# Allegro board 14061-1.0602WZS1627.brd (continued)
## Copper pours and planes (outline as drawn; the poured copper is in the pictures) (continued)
DCBATOUT on BOTTOM: 57.07,64.12 56.88,64.31 56.88,69.22 57.26,69.6 61.32,69.6 61.58,69.34 61.58,64.26 61.44,64.12
DCBATOUT on L3: 53.51,72.02 54.74,70.79 54.74,70.76 55.02,70.48 59.98,70.48 60.61,69.85 60.61,68.17 59.75,67.31 50.96,67.31 50.68,67.03 48.17,67.03 47.89,67.31 46.52,67.31 46.24,67.03 43.95,67.03 41.56,69.42 41.56,71.77 41.82,72.02
DCBATOUT on L3: 144.31,142.88 144.31,127.38 143.92,127 143.92,119.61 144.4,119.13 144.4,115.34 144.4,115.34 144.4,114.63 145.7,113.33 145.7,111.28 146.11,110.87 146.11,110.34 146.92,109.52 148.55,109.52 148.88,109.86 148.88,111.58 148.15,112.31 148.15,114.8 146.74,116.2 146.74,124.18 146.92,124.36 146.97,124.36 147.99,125.37 147.99,129.92 148.14,130.07 148.14,142.7 147.58,143.26 144.69,143.26
DCBATOUT on L4: 54.77,67.18 52.87,69.09 42.32,69.09 41.82,68.58 35.35,68.58 33.41,66.63 33.41,59.45 37.4,55.46 37.4,52.28 36.97,51.85 35.56,51.85 30.49,56.92 30.49,68.12 36.99,74.62 43.55,74.62 44.48,75.55 44.48,77.85 43.98,78.36 41.63,78.36 40.43,79.56 40.43,118.31 40.44,118.32 40.44,118.82 42.09,120.47 42.09,124.61 43.23,125.74 43.24,125.74 43.74,126.24 46.97,126.24 47.85,125.36 47.85,119.64 46.71,118.5 46.71,86.22 51.47,81.45 51.47,80.14 51.47,79.11 52.48,78.11 53.51,78.11 60.6,71.02 60.6,67.74 60.05,67.18 ; 1 cut-out
DCBATOUT_1D8V on TOP: 31.1,209.19 30.74,209.55 30.74,214.71 30.12,215.33 29.94,215.33 29.88,215.39 29.88,216.31 29.45,216.74 29.45,222.78 29.67,223.01 33.41,223.01 33.68,222.75 33.68,220.56 35.42,218.82 35.42,215.9 36.36,214.96 36.36,209.37 36.18,209.19 ; 2 cut-outs
DCBATOUT_1D8V on BOTTOM: 30.84,219.25 30.18,219.91 30.18,222.88 30.36,223.06 33.64,223.06 33.99,222.71 33.99,220.12 33.13,219.25
DDR_VDDQ on TOP: 86.58,160.14 86.35,160.37 86.35,160.52 87.19,161.36 87.57,161.36 87.98,160.95 87.98,160.67 87.45,160.14
DDR_VDDQ on TOP: 87.18,168.66 86.37,169.47 86.37,169.65 86.55,169.82 87.36,169.82 87.94,169.24 87.94,169.06 87.54,168.66
DDR_VDDQ on BOTTOM: 132.34,147.9 131.74,148.5 95.7,148.5 93.53,150.67 92.23,150.67 88.81,154.09 88.81,158.88 87.36,160.32 87.36,160.99 87.52,161.15 88.13,161.15 88.71,160.57 90.36,160.57 90.93,161.14 92.48,161.14 92.81,161.48 92.81,162.33 92.97,162.49 93.65,162.49 93.91,162.75 93.91,164.07 94.51,164.66 94.51,165.08 94.83,165.4 94.83,165.68 95.08,165.93 95.08,167.07 94.92,167.23 94.11,167.23 93.99,167.36 93.99,168.15 93.85,168.28 93.65,168.28 93.64,168.29 87.75,168.29 87.43,168.61 87.43,169.34 87.84,169.75 87.84,176.86 89.14,178.16 89.14,179.17 91.52,181.56 97.85,181.56 98.97,182.68 130.59,182.68 130.77,182.5 130.77,176.58 131.33,176.02 133.08,176.02 133.15,176.1 134.15,176.1 135.24,175.01 136.81,175.01 136.81,175.02 137.7,175.91 139.56,175.91 140.19,175.27 140.19,154.48 140.95,153.72 140.95,151.21 140.33,150.58 140.33,149.9 138.34,147.9 ; 38 cut-outs
DPLL_PVDD on TOP: 90.51,98.02 90.38,98.15 90.38,99.9 90.94,100.46 90.94,102.03 91.17,102.26 91.73,102.26 92.13,101.85 92.13,101.52 91.96,101.35 91.96,100.81 92.24,100.53 92.24,99.95 91.92,99.63 91.92,99.45 92.11,99.26 92.11,98.98 91.65,98.53 91.22,98.53 90.71,98.02
DPLL_PVDD on BOTTOM: 94.14,96.06 93.84,96.37 93.23,96.37 92.77,96.82 92.77,97.43 92.08,98.12 92.08,98.45 91.65,98.88 91.65,100.56 91.5,100.71 91.5,101.68 91.65,101.83 92.08,101.83 92.21,101.7 92.21,100.84 92.54,100.51 92.97,100.51 93.1,100.38 93.1,98.86 93.68,98.27 93.68,97.49 94.19,96.98 94.7,96.98 94.93,96.75 94.93,96.32 94.67,96.06 ; 3 cut-outs
DPLL_VDDC on TOP: 91.09,102.49 90.84,102.74 90.84,103.12 90.33,103.63 90.33,104.27 90.58,104.52 91.6,104.52 92.11,104.01 92.11,103.5 91.6,103 91.6,102.62 91.47,102.49
DPLL_VDDC on BOTTOM: 90.69,103.35 90.61,103.43 90.61,103.76 90.86,104.01 90.86,104.65 91.83,105.61 93,105.61 93.45,106.07 93.45,107.72 93.71,107.98 95.08,107.98 95.24,107.81 95.24,104.91 94.8,104.47 92.74,104.47 92.41,104.14 92.41,103.58 92.18,103.35 ; 2 cut-outs
DPLL_VDDC on L4: 90.33,103.68 90.21,103.56 90.21,103.35 89.01,103.35 88.65,103 88.65,99.77 89.09,99.34 89.09,97.44 89.28,97.24 91.06,97.24 91.51,97.69 91.51,99.3 91.5,99.31 91.5,99.95 92.72,101.17 92.72,103.89 92.46,104.14 90.61,104.14 90.33,103.86
ISW_1 on BOTTOM: 39.96,35 39.78,35.18 39.78,38.23 39.25,38.76 37.09,38.76 36.71,38.38 36.71,36.7 35.47,35.46 33.94,35.46 33.82,35.59 33.82,36.47 34.22,36.88 34.96,36.88 35.62,37.54 35.62,42.85 36.28,43.51 41.41,43.51 41.94,42.98 41.94,35.13 41.82,35
LX on TOP: 29.75,35.46 29.75,43.56 30.01,43.81 30.03,43.81 31.02,44.81 34.17,44.81 34.81,44.17 34.81,43.16 33.78,42.13 33.78,35.63 33.33,35.18 30.03,35.18
LX on BOTTOM: 31.96,37.29 31.86,37.39 31.86,38.48 31.35,38.99 29.37,38.99 28.99,39.37 28.99,43.43 29.37,43.81 29.37,43.81 29.82,44.26 35.09,44.26 35.3,44.05 35.3,43.47 34.45,42.62 34.45,38.23 34.44,38.21 34.44,37.73 33.99,37.29
MCT_R on TOP: 59.98,9.65 59.85,9.78 59.85,14.1 59.98,14.22 63.93,14.22 64.15,14.44 64.15,17.89 64.29,18.03 66.34,18.03 66.45,17.92 66.45,14.61 64.55,12.7 63.41,12.7 63.28,12.57 63.28,10.41 62.52,9.65 ; 2 cut-outs
MCT_R_1 on BOTTOM: 64.3,11.68 64.17,11.81 64.17,17.91 64.3,18.03 66.33,18.03 66.45,17.91 66.45,11.94 66.2,11.68
MEM_VTT on TOP: 141.04,129.25 140.56,129.73 140.56,130.32 140.57,130.32 141.26,131.01 141.26,139.7 141.64,140.08 145.96,140.08 146.21,139.83 146.21,138.56 146.08,138.43 143.29,138.43 142.91,138.05 142.91,130.42 141.74,129.25
MEM_VTT on BOTTOM: 133.97,128.27 133.71,128.52 131.33,128.52 131.25,128.6 131.25,129.36 131.33,129.44 137.78,129.44 138.41,130.07 141.38,130.07 141.69,129.77 141.69,129.46 141.1,128.88 140.95,128.88 140.34,128.27 ; 9 cut-outs
MPV18 on BOTTOM: 78.75,87.3 78.62,87.43 78.62,92.23 78.42,92.44 78.01,92.44 77.91,92.54 77.91,93.1 78.01,93.2 78.54,93.2 78.97,92.77 78.97,92.28 79.18,92.08 79.18,91.04 79.3,90.91 79.3,87.41 79.2,87.3
PWR_0P95V_LX on TOP: 118.91,106.3 118.52,106.68 118.52,112.78 118.78,113.03 120.94,113.03 121.57,113.67 121.57,114.94 121.83,115.19 123.22,115.19 123.35,115.06 123.35,113.41 123.48,113.28 124.87,113.28 125.13,113.03 125.13,109.47 125,109.35 123.99,109.35 123.35,108.71 123.35,106.43 123.22,106.3
PWR_0P95V_VIN on TOP: 123.99,104.9 123.86,105.03 123.86,108.58 124.11,108.84 130.59,108.84 130.84,108.58 130.84,105.16 130.59,104.9
PWR_1D15V_A on TOP: 92.87,203.84 91.73,204.98 91.73,210.69 91.98,210.95 96.55,210.95 96.93,210.57 96.93,204.34 96.43,203.84 ; 6 cut-outs
PWR_1D15V_LX on TOP: 92.74,214.76 92.62,214.88 92.62,219.07 92.74,219.2 94.01,219.2 94.39,218.82 96.17,218.82 96.22,218.77 96.22,217.68 97.11,216.79 97.11,215.11 96.76,214.76
PWR_1D15V_PVIN on TOP: 91.37,221.11 90.99,221.49 90.99,224.59 91.17,224.76 93.53,224.76 93.66,224.64 93.66,223.39 94.36,222.68 95.56,222.68 95.79,222.45 95.79,221.16 95.74,221.11 ; 4 cut-outs
PWR_1P05V_LX on TOP: 37.75,195.83 37.37,196.22 37.37,199.01 37.22,199.16 36.18,199.16 36.05,199.29 36.05,200.69 36.18,200.81 38.08,200.81 38.34,201.07 38.34,202.46 38.46,202.59 42.02,202.59 42.15,202.46 42.15,201.45 42.65,200.94 45.19,200.94 45.27,200.86 45.27,199.39 45.32,199.34 45.32,196.75 44.41,195.83 ; 2 cut-outs
PWR_1P05V_LX on L3: 38.51,202.56 41.94,202.56 42.07,202.44 42.07,201.55 42.71,200.91 45.25,200.91 45.25,196.72 44.36,195.83 37.75,195.83 37.37,196.22 37.37,199.01 37.24,199.14 36.23,199.14 36.1,199.26 36.1,200.66 36.23,200.79 38.01,200.79 38.39,201.17 38.39,202.44
PWR_1P05V_VIN on TOP: 43.06,201.22 42.71,201.57 42.71,212.01 43.04,212.34 47.89,212.34 48.12,212.12 48.12,207.92 48.39,207.65 48.39,204.95 47.96,204.52 47.12,204.52 46.79,204.19 46.79,201.47 46.54,201.22
PWR_3V_PHASE2 on TOP: 77.38,48.59 77.25,48.72 77.25,50.83 77.43,51 79.15,51 79.54,51.38 79.54,53.04 79.28,53.29 75.73,53.29 75.73,56.59 75.85,56.72 77.38,56.72 77.5,56.85 77.5,58.88 77.63,59 82.46,59 83.09,58.37 83.09,48.84 82.84,48.59
PWR_5V_PHASE1 on TOP: 78.11,59.84 77.5,60.45 77.5,62.74 77.63,62.87 79.03,62.87 79.54,63.37 79.54,64.9 79.28,65.15 75.98,65.15 75.85,65.28 75.85,68.71 76.11,68.96 78.77,68.96 79.03,69.22 79.03,70.59 79.26,70.83 82.7,70.83 83.6,69.93 83.6,60.15 83.29,59.84
PWR_CHG_PHASE on BOTTOM: 38.26,54.99 38.13,55.12 38.13,57.66 37.75,58.04 36.15,58.04 36.1,57.99 36.1,56.74 36,56.64 34.07,56.64 33.82,56.9 33.82,58.55 34.32,59.05 34.32,61.98 34.58,62.23 40.55,62.23 41.18,61.59 41.18,59.31 41.82,58.67 41.82,55.12 41.69,54.99
PWR_DDR4_LDOIN on TOP: 150.55,136.17 150.3,136.42 149.34,136.42 148.68,137.08 148.68,137.94 148.72,137.98 148.75,137.98 148.75,138.46 149,138.71 149.94,138.71 150.2,138.46 150.2,137.46 151.19,136.47 151.19,136.32 151.04,136.17
PWR_DDR4_LX on TOP: 153.27,150.85 152.94,151.18 152.94,154.56 152.69,154.81 148.62,154.81 148.37,155.07 148.37,156.67 148.22,156.82 148.22,158.98 149.13,159.89 158.78,159.89 159.04,159.64 159.04,151.03 158.86,150.85 ; 2 cut-outs
PWR_DDR4_VIN on TOP: 148.6,144.07 148.16,144.5 144.26,144.5 144.16,144.6 144.16,153.67 144.88,154.39 152.1,154.39 152.18,154.31 152.18,144.4 151.85,144.07
PWR_DDR4_VIN on BOTTOM: 147.4,144.4 146.79,145.01 146.79,148.41 147.1,148.72 152.05,148.72 152.18,148.59 152.18,144.53 152.05,144.4
PWR_DDR4_VTT on TOP: 147.1,134.24 146.85,134.49 146.85,139.95 146.97,140.08 147.99,140.08 148.12,139.95 148.12,137.39 149.32,136.18 149.47,136.18 149.64,136.02 149.64,135.89 149.51,135.76 149.23,135.76 148.62,135.16 148.62,134.37 148.5,134.24
PWR_V1P5A on BOTTOM: 163.18,76.16 162.96,76.38 162.96,76.98 162.95,76.99 162.95,82.55 163,82.6 164.88,82.6 164.98,82.5 164.98,78.46 164.45,77.93 164.45,76.33 164.27,76.16 ; 7 cut-outs
PWR_V1P8A on TOP: 35.62,177.52 35.34,177.8 30.77,177.8 30.77,179.96 31.02,180.21 32.67,180.21 33.24,180.78 36.29,180.78 36.36,180.72 36.36,177.62 36.25,177.52 ; 6 cut-outs
PWR_V1P24A on TOP: 45.8,172.47 45.73,172.54 45.73,176.02 46.03,176.33 49.66,176.33 49.88,176.11 49.88,172.63 49.72,172.47 ; 6 cut-outs
PWR_VCC0_SW on BOTTOM: 55.35,203.89 54.64,204.6 54.64,205.66 55.82,206.84 55.82,208.83 56.04,209.04 57.26,209.04 57.31,208.99 60.28,208.99 60.79,209.5 60.79,212.65 60.99,212.85 66.2,212.85 66.48,212.57 66.48,208.64 66.61,208.51 68.69,208.51 68.7,208.5 68.78,208.5 68.99,208.28 68.99,205.1 67.77,203.89 ; 2 cut-outs
PWR_VCC0_VIN on TOP: 54.82,210.01 54.44,210.39 54.44,217.12 56.27,218.95 58.45,218.95 59.39,218.01 59.39,210.39 59.01,210.01
PWR_VCC0_VIN on BOTTOM: 54.44,209.3 54.31,209.42 54.31,219.13 54.43,219.24 59.43,219.24 59.77,218.9 59.77,209.35 59.72,209.3 ; 2 cut-outs
PWR_VCORE_VCC0 on TOP: 83.85,167.41 83.62,167.64 83.62,169.01 83.22,169.42 83.22,169.67 84.11,170.56 85.02,170.56 85.17,170.41 85.17,169.52 84.74,169.09 84.74,168.58 85.55,167.77 85.55,167.49 85.48,167.41
PWR_VCORE_VCC0 on TOP: 56.52,187.32 55.51,188.34 55.51,192.41 56.24,193.14 57.64,193.14 58.64,194.13 58.64,198.74 58.85,198.96 59.58,198.96 59.83,199.21 70.85,199.21 71.46,198.6 71.46,188.29 70.49,187.32 ; 13 cut-outs
PWR_VCORE_VCC0 on TOP: 83.65,164.41 83.55,164.52 83.55,164.77 83.6,164.82 83.6,165.1 82.76,165.94 82.76,166.32 83.19,166.75 84.97,166.75 85.12,166.6 85.12,166.42 85.02,166.32 85.02,165.96 85.3,165.68 85.35,165.68 85.55,165.48 85.55,165.28 85.43,165.15 85.43,164.9 85.61,164.72 85.61,164.54 85.48,164.41 85.28,164.41 85.15,164.54 84.08,164.54 83.95,164.41
PWR_VCORE_VCC0 on BOTTOM: 56.78,187.07 55.91,187.93 55.91,191.64 55.93,191.65 55.93,192.9 57.69,194.67 57.69,200.79 58.02,201.12 62.64,201.12 63.1,200.66 69.78,200.66 71.73,198.71 71.73,188.66 70.15,187.07
PWR_VCORE_VCC0 on BOTTOM: 83.7,164.31 83.35,164.67 83.35,165.61 83.19,165.76 82.89,165.76 82.48,165.35 82.05,165.35 81.87,165.53 81.87,166.09 82.05,166.27 82.71,166.27 82.75,166.3 82.75,167.04 83.6,167.89 83.6,170.23 83.78,170.41 84.59,170.41 84.87,170.13 84.87,169.73 84.98,169.62 85.72,169.62 85.85,169.49 85.85,168.99 85.93,168.91 86.27,168.91 86.52,168.66 86.52,168.28 86.14,167.89 85.89,167.89 85.63,167.64 85.63,167.53 84.65,166.55 84.65,166.22 85.19,165.68 85.47,165.68 85.6,165.54 85.6,164.48 85.44,164.31 ; 4 cut-outs
PWR_VCORE_VCC0 on L3: 83.6,164.34 83.37,164.57 82.66,164.57 81.15,166.08 81.15,169.19 80.61,169.72 76.69,169.72 76.18,170.23 76.18,178.1 75.37,178.92 75.37,184.08 73.87,185.58 57.77,185.58 56.11,187.24 56.11,190.91 57.23,192.03 59.9,192.03 63.05,195.18 65.97,195.18 67.59,196.8 67.59,196.8 69.35,198.56 73.24,198.56 73.88,197.92 81.62,197.92 86.14,193.39 86.14,187.89 86.58,187.45 86.58,180.66 86.52,180.59 86.52,180.47 87.16,179.83 87.16,175.43 87.7,174.89 87.7,164.85 87.18,164.34
PWR_VCORE_VGG on TOP: 37.68,140.34 37.17,140.84 37.17,145.54 37.37,145.75 39.96,145.75 44.74,150.52 44.74,155.73 43.01,157.45 38.54,157.45 38.11,157.89 38.11,162.18 39.1,163.17 48.75,163.17 50.36,161.56 50.36,160.36 52.87,157.86 52.87,148.34 51.82,147.29 51.82,145.34 52.26,144.91 55.63,144.91 58.43,147.7 58.43,151.36 59.47,152.4 61.5,152.4 62.09,151.82 62.09,145.87 56.55,140.34
PWR_VCORE_VGG on TOP: 82.61,159.44 82.41,159.64 82.41,161.26 83.29,162.15 83.29,162.51 83.22,162.59 83.22,162.79 83.35,162.92 83.52,162.92 83.62,162.81 83.88,162.81 84.06,162.99 84.06,163.3 84.01,163.35 84.01,163.5 84.11,163.6 85.89,163.6 85.94,163.55 85.94,163.35 85.54,162.95 85.54,162.49 85.62,162.41 85.62,160.69 85.49,160.56 85.18,160.56 85.06,160.68 84.84,160.68 84.73,160.57 84.73,160.33 84.8,160.27 84.8,159.85 84.38,159.44 84.26,159.44 84.26,159.44
PWR_VCORE_VGG on BOTTOM: 83.7,159.49 83.45,159.74 82.73,159.74 82.46,160.02 82.46,161.21 82.61,161.37 82.61,161.7 82.76,161.86 83.07,161.86 83.38,162.16 83.38,162.42 83.48,162.52 83.48,162.52 83.64,162.68 83.9,162.68 84.54,163.32 85.5,163.32 85.62,163.45 86.4,163.45 86.53,163.31 86.53,161.78 85.84,161.08 85.84,160.64 85.9,160.58 85.9,159.62 85.77,159.49 ; 3 cut-outs
PWR_VCORE_VGG on L3: 81.49,160.27 82.58,161.36 82.58,161.83 82.75,162 83.17,162 83.35,162.18 83.35,162.59 83.5,162.74 83.51,162.74 84.13,163.36 84.69,163.36 84.69,163.36 85.39,163.36 85.76,162.99 87.73,162.99 90,160.73 90,160.71 90.51,160.2 90.51,152.88 87.97,150.34 86.37,150.34 86.24,150.22 86.24,150.16 85.63,149.56 83.62,149.56 82.58,148.51 77.6,148.51 77.43,148.34 77.43,148.29 76.72,147.57 72.73,147.57 71.48,146.33 71.03,146.33 69.98,145.29 63.79,145.29 62.39,143.89 60.84,143.89 58.73,141.78 42.2,141.78 41.23,142.75 41.23,146.2 44.73,149.7 44.73,156.45 43.7,157.48 38.69,157.48 38.18,157.99 38.18,162.28 39.02,163.12 51.09,163.12 53.18,161.02 53.18,159.31 55.39,157.1 56.68,157.1 57.51,157.94 64.8,157.94 65.44,158.57 71.76,158.57 72.22,158.12 74.05,158.12 74.7,158.76 76.37,158.76 77.88,160.27
PWR_VCORE_VNN on TOP: 80.98,160.2 80.83,160.35 80.83,163.65 80.96,163.78 80.96,163.98 80.81,164.13 80.81,164.36 80.93,164.49 81.08,164.49 81.26,164.31 81.52,164.31 82.3,165.1 82.74,165.1 82.76,165.07 82.76,164.11 82.46,163.8 82.46,162.18 82,161.72 82,160.32 81.87,160.2
PWR_VCORE_VNN on TOP: 56.5,177.42 55.48,178.44 43.85,178.44 38.64,183.64 38.64,187.45 38.9,187.71 46.01,187.71 46.26,187.45 46.26,185.57 48.81,183.02 50.96,183.02 52.22,181.76 56.83,181.76 58,180.59 67.34,180.59 67.6,180.34 67.6,178.54 67.24,178.18 66.4,178.18 66.17,177.95 66.17,177.55 66.05,177.42 ; 4 cut-outs
PWR_VCORE_VNN on BOTTOM: 80.27,159.77 80.21,159.84 80.21,160.44 80.68,160.91 80.68,161.89 80.81,162.02 80.93,162.02 81.16,162.25 81.16,163.89 81.37,164.11 81.99,164.11 82.16,163.94 82.16,163.37 82.48,163.05 82.48,162.28 81.83,161.63 81.83,161.54 81.82,161.53 81.82,159.92 81.67,159.77 ; 4 cut-outs
PWR_VCORE_VNN on L3: 66.97,160.49 64.75,162.71 64.75,166.04 64.47,166.32 64.45,166.32 62.52,168.25 62.52,179.32 63.15,179.96 66.91,179.96 67.6,179.27 67.6,167.87 69.92,165.56 81.16,165.56 82.32,164.4 82.32,162.73 82.3,162.71 82.3,161.33 81.46,160.49
PWR_VGA_CORE_PHASE1 on TOP: 127.39,89.97 127.33,90.03 124.15,90.03 123.45,90.73 123.45,96.06 122.44,97.08 122.44,102.29 122.82,102.67 123.32,102.67 123.39,102.6 124.15,102.6 124.21,102.67 127.13,102.67 128.4,103.94 129.55,103.94 129.67,103.81 129.67,96.06 129.93,95.81 133.1,95.81 133.23,95.68 133.23,90.09 133.1,89.97
PWR_VGA_CORE_PHASE1 on BOTTOM: 123.07,90.09 122.44,90.73 122.44,102.16 122.94,102.67 129.55,102.67 129.67,102.54 129.67,96.06 129.93,95.81 132.98,95.81 133.23,95.55 133.23,90.22 133.1,90.09
PWR_VGG_SW on TOP: 31.91,142.57 31.78,142.7 31.78,146.74 31.45,147.07 28.05,147.07 27.74,147.37 27.74,153.44 29.24,154.94 33.41,154.94 34.37,155.91 41.03,155.91 41.51,155.42 41.51,152.68 41.26,152.43 38.31,152.43 37.51,151.63 37.51,147.31 36.79,146.58 36.79,143.28 36.08,142.57
PWR_VGG_SW on BOTTOM: 31.78,142.62 31.66,142.75 31.66,146.94 31.4,147.19 27.97,147.19 27.77,147.4 27.77,153.09 27.85,153.16 31.53,153.16 31.88,153.52 31.88,154.81 31.9,154.83 31.9,155.44 32.21,155.75 37.17,155.75 38.01,154.91 38.01,147.78 36.81,146.58 36.81,143.31 36.14,142.63 35.3,142.63 35.29,142.62 ; 2 cut-outs
PWR_VGG_VIN on TOP: 22.03,141.38 21.31,142.1 21.31,144.37 20.76,144.92 20.76,148.49 21.06,148.79 22.94,148.79 25.41,146.32 26.75,146.32 27.27,145.8 27.27,142.02 26.63,141.38
PWR_VGG_VIN on BOTTOM: 21.37,140.84 21.24,140.97 21.24,145.97 21.7,146.43 31.15,146.43 31.28,146.3 31.28,140.97 31.15,140.84 ; 2 cut-outs
RING2 on TOP: 168,74.85 166.81,76.05 166.81,76.48 167.09,76.76 168.31,76.76 169.12,75.95 170.37,75.95 171.31,76.89 173.39,76.89 173.64,76.63 173.64,75.77 173.54,75.67 171.84,75.67 171.03,74.85 ; 2 cut-outs
SB3V on TOP: 120.07,68.07 119.12,69.02 118.92,69.02 117.84,70.1 117.2,70.1 117.03,69.93 116.24,69.93 115.83,69.52 114.74,69.52 113.55,70.71 112.22,70.71 112.02,70.51 112.02,69.32 111.13,69.32 110.47,69.98 110.47,71.25 111.36,72.14 120.1,72.14 120.4,71.83 120.4,69.72 120.63,69.49 120.63,68.22 120.48,68.07 ; 2 cut-outs
SB3V on TOP: 163.69,85.06 162.82,85.93 162.82,88.06 162.21,88.67 162.21,91.01 162.24,91.03 163.33,91.03 164.07,90.3 164.07,89.94 164.09,89.92 164.09,89.36 166.12,87.33 169.5,87.33 170.04,87.86 171.08,87.86 171.64,87.3 171.64,85.34 171.36,85.06 ; 1 cut-out
SB3V on BOTTOM: 122.54,57.7 121.9,58.34 121.9,58.9 122.03,59.03 122.61,59.03 123.2,58.45 124.79,58.45 124.9,58.33 124.9,57.89 124.72,57.7
SB3V on BOTTOM: outline of 92 points within 127.41,82.85 178.39,225.91 ; 8 cut-outs
SB3V on BOTTOM: 29.83,10.03 29.78,10.08 27.67,10.08 27.57,10.18 27.57,11.07 27.92,11.42 27.92,14.3 28.01,14.39 28.67,14.39 28.82,14.24 28.82,13.43 28.51,13.11 28.51,12.29 28.68,12.12 30.44,12.12 30.54,12.01 30.54,11.51 31.1,10.95 31.1,10.26 30.87,10.03 ; 3 cut-outs
SB3V on BOTTOM: 135.82,53.51 135.64,53.69 135.64,56.83 134.35,58.11 134.35,61.41 134.6,61.66 135.49,61.66 135.91,62.09 135.91,62.69 136.71,63.49 136.88,63.49 136.89,63.47 137.3,63.47 137.3,63.45 137.92,62.83 137.92,60.13 137.39,59.61 136.25,59.61 135.88,59.24 135.88,58.44 136.45,57.87 136.45,53.65 136.3,53.51 ; 3 cut-outs
SB3V on L3: 170.72,87.76 169.02,87.76 167.62,86.36 167.62,85.39 167.63,85.38 167.63,84.82 167.93,84.53 169.65,84.53 171.1,85.98 171.1,87.38
SB3V on L4: 168.96,86.02 169.35,85.63 170.71,85.63 171.36,86.28 171.36,88.13 171.35,88.14 171.35,88.64 171.06,88.93 169.7,88.93 168.96,88.19
SB5V on TOP: 164.96,91.49 164.04,92.41 162.21,92.41 162.16,92.46 162.16,94.16 162.42,94.41 163.08,94.41 163.61,93.88 167.37,93.88 168.21,94.72 169.81,94.72 170.04,94.49 170.04,93.42 169.3,92.68 169.3,91.82 168.97,91.49 ; 3 cut-outs
SB5V on TOP: 25.5,12.69 25.46,12.73 24.62,12.73 24.47,12.88 24.47,14.86 24.06,15.27 24.06,16.48 24.37,16.79 25.38,16.79 25.66,16.51 25.66,14.76 25.74,14.68 25.74,12.93
SB5V on BOTTOM: 23.27,5.05 23.2,5.12 23.2,8.61 23.96,9.37 23.96,10.34 23.93,10.36 23.93,12.42 24.98,13.46 26.6,13.46 26.78,13.28 26.78,12.75 26.53,12.5 26.07,12.5 25.43,11.86 25.43,9.09 24.98,8.64 24.97,8.64 24.56,8.23 24.56,5.2 24.42,5.05 ; 1 cut-out
SB5V on BOTTOM: 119.74,57.76 119.62,57.89 119.62,60.05 119.87,60.3 121.39,60.3 121.5,60.2 121.5,58.12 121.14,57.76
SB5V on BOTTOM: 164.6,86 164.59,86.02 164.26,86.02 164.19,86.08 164.19,89.53 164.22,89.56 164.22,92.91 165.08,93.78 165.08,94.51 165.97,95.4 167.85,95.4 169.02,94.24 169.02,91.66 168.57,91.22 165.9,91.22 165.34,90.65 165.34,88.47 164.88,88.01 164.88,86.06 164.83,86
SLEEVE on TOP: 167.44,72.19 167.01,72.62 167.01,73.05 168.46,74.5 171.28,74.5 171.34,74.56 171.62,74.56 172.07,74.12 172.07,73.69 171.76,73.38 169.1,73.38 167.9,72.19 ; 2 cut-outs
USBVCC14 on TOP: 169.98,98.12 169.6,98.5 169.6,99.19 168.99,99.8 168.99,101.35 169.25,101.6 170.01,101.6 170.37,101.96 170.37,102.59 169.71,103.25 169.71,103.63 169.96,103.89 171.56,103.89 172.09,103.35 172.09,101.65 173.85,99.9 173.85,98.78 173.18,98.12 ; 2 cut-outs
USBVCC14 on TOP: 169.76,119.76 169.31,120.21 169.31,122.09 169.03,122.36 167.18,122.36 165.34,120.52 164.73,120.52 164.22,120.02 160.89,120.02 160.89,120.02 160.53,120.02 160,120.55 160,121.13 159.76,121.37 159.76,121.83 159.87,121.93 161.86,121.93 163.41,123.48 163.41,125.4 163.99,125.98 170.29,125.98 173.62,122.66 173.62,121.89 173.31,121.59 172.55,121.59 171.71,120.75 171.71,120.12 171.36,119.76 ; 2 cut-outs
USBVCC14 on L4: 173.52,122.76 171.05,122.76 170.21,121.91 170.21,104.61 169.58,103.99 169.58,103.25 170.09,102.74 170.47,102.74 170.47,102.72 170.62,102.57 170.62,98.14 171.19,97.57 172.94,97.57 172.94,97.58 173.23,97.87 173.23,99.61 174.08,100.46 174.08,103.91 173.35,104.63 173.35,108.69 174.49,109.83 174.49,110.54 176.55,112.6 176.55,121.58 175.39,122.74 173.53,122.74
USBVCC56 on TOP: 94.9,15.88 90.08,20.7 90.08,28.96 90.46,29.34 91.85,29.34 91.98,29.21 91.98,27.18 92.62,26.54 100.36,26.54 100.87,27.05 100.87,30.23 99.09,32 98.46,32 96.68,33.78 96.68,38.86 99.86,42.04 102.27,42.04 102.9,41.4 102.9,39.88 102.14,39.12 99.47,39.12 98.46,38.1 98.46,35.56 100.24,33.78 100.24,33.4 103.03,30.61 103.03,23.62 102.9,23.5 102.9,16.64 102.14,15.88 ; 4 cut-outs
USBVCCTP on BOTTOM: 27.02,3.95 26.03,4.93 24.95,4.93 24.84,5.04 24.84,8.01 25.21,8.38 26.46,8.38 26.48,8.35 26.48,7.01 26.9,6.6 28.38,6.6 28.57,6.41 28.57,5.08 27.44,3.95 ; 2 cut-outs
V_1P5_HDMI on BOTTOM: 122.28,18.72 122.05,18.95 122.05,22.38 121.7,22.73 121.7,25.88 121.45,26.14 121.45,28.42 121.75,28.73 122.46,28.73 123.12,28.07 123.12,26.92 123.73,26.31 123.73,22.89 123.3,22.45 123.3,18.82 123.2,18.72
V_1P5_HDMI on L3: 135.23,41.1 129.64,41.1 129.26,40.72 129.26,39.37 129.69,38.94 129.69,34.57 129.12,34 127.89,34 125.72,31.83 125.72,30.93 124.68,29.89 121.45,29.89 121.17,29.61 121.17,27.81 121.4,27.58 126.07,27.58 128.86,30.37 128.86,31.44 129.17,31.75 135.81,31.75 136.12,32.05 136.12,40.21 ; 1 cut-out
V_1P05_LAN on BOTTOM: 39.91,13.46 39.78,13.59 39.78,17.02 39.53,17.27 38.82,17.27 38.74,17.35 38.74,17.98 38.92,18.16 39.78,18.16 40.55,17.4 40.55,13.59 40.42,13.46 ; 1 cut-out
V_1P05_LAN on BOTTOM: 32.98,14.22 32.82,14.38 32.82,15.06 33.15,15.39 33.15,17.7 33.33,17.88 34.25,17.88 34.35,17.78 34.35,16.97 34.3,16.92 34.3,15.04 33.48,14.22 ; 2 cut-outs
V_1P05_LAN on L4: 40.32,17.2 39.33,17.2 39.02,16.89 39.02,14.1 38.32,13.4 35.4,13.4 35.09,13.72 35.09,14.48 34.32,15.24 33.05,15.24 32.8,14.99 32.8,14.48 33.05,14.22 33.56,14.22 33.69,14.1 33.69,13.34 33.43,13.08 33.05,13.08 32.93,12.95 32.93,11.94 33.05,11.81 36.36,11.81 37.12,11.05 37.63,11.05 37.88,11.3 37.88,11.56 38.26,11.94 39.4,11.94 40.67,13.21 40.67,16.84
V_3P3_A on TOP: 132.27,49.02 130.59,50.7 130.59,51.97 130.67,52.04 132.32,52.04 132.34,52.02 132.34,51.66 132.16,51.49 131.63,51.49 131.55,51.41 131.55,50.9 132.49,49.96 133.43,49.96 133.59,49.81 133.59,49.23 133.38,49.02
V_3P3_A on TOP: 157.87,88.44 157.46,88.85 157.46,90.78 157.69,91.01 160.76,91.01 160.84,90.93 160.84,88.82 160.46,88.44
V_3P3_A on TOP: 123.3,70.54 123.2,70.64 123.2,72.77 123.39,72.97 123.39,73.37 123.58,73.56 125.1,73.56 125.51,73.15 125.51,70.89 125.36,70.74 125.2,70.74 125,70.54 ; 1 cut-out
V_3P3_A on TOP: 42.71,170.31 42.59,170.42 42.59,173.47 42.32,173.74 40.7,173.74 39.43,175.01 38.64,175.01 35.97,172.34 28.86,172.34 27.59,173.61 27.59,178.82 27.34,179.07 25.66,179.07 25.15,179.58 21.75,179.58 20.35,180.97 20.35,182.25 20.61,182.5 27.72,182.5 30.46,179.76 30.46,174.93 30.64,174.75 34.83,174.75 37.35,177.27 40.22,177.27 40.52,176.96 42.12,176.96 42.86,176.23 44.03,176.23 45.42,174.83 45.42,170.43 45.3,170.31 ; 4 cut-outs
V_3P3_A on TOP: 93.11,45.09 92.46,45.73 92.46,46.13 94.67,48.34 94.72,48.34 95.14,48.76 97.77,48.76 98.43,49.43 98.43,55.17 98.6,55.33 100.45,55.33 101.63,56.52 104.17,56.52 104.3,56.39 104.3,54.31 104.24,54.24 104.24,52.64 104.17,52.58 103.41,52.58 103.16,52.32 103.16,50.16 99.27,46.27 96.4,46.27 95.21,45.09 ; 3 cut-outs
V_3P3_A on TOP: 130.74,64.26 130.69,64.31 130.69,64.54 133.61,67.46 134.7,67.46 134.96,67.21 134.96,66.52 134.86,66.42 134.4,66.42 134.34,66.48 134.26,66.48 134.15,66.36 134.15,66.14 132.27,64.26 ; 1 cut-out
V_3P3_A on TOP: 116.4,65.07 116.15,65.33 116.15,66.84 116.29,66.98 117.42,66.98 117.64,66.76 117.64,66.7 117.71,66.62 117.71,65.15 117.64,65.07
V_3P3_A on BOTTOM: 158.68,89.38 157.56,90.5 157.56,91.03 157.61,91.08 159.19,91.08 159.75,90.53 160.46,90.53 160.54,90.45 160.54,89.53 160.38,89.38 ; 1 cut-out
V_3P3_A on L3: 157.77,91.41 157.27,90.92 157.27,87.97 154.77,85.47 154.77,85.27 154.74,85.24 154.74,84.76 155.02,84.48 156.85,84.48 159.49,87.12 159.49,90.12 158.2,91.41
V_3P3_A on L3: 101.51,56.39 100.36,56.39 99.47,55.5 99.47,51.94 100.11,51.31 102.78,51.31 106.28,54.81 106.28,62.66 107.75,64.14 110.07,64.14 111.25,65.32 112.48,65.32 112.48,65.3 113.39,64.39 115.12,64.39 115.12,64.34 115.7,63.75 119.79,63.75 120.94,64.9 131.61,64.9 132.7,65.99 133.64,65.99 134.12,65.51 137.9,65.51 139.01,66.61 139.01,67.04 139.73,67.77 139.73,68.33 140.29,68.88 140.29,70.28 140.08,70.5 137.88,70.5 136.27,68.88 132.27,68.88 131.81,68.43 106.81,68.43 102.24,63.86 102.24,57.12
V_3P3_LAN on BOTTOM: 31.73,8.99 31.66,9.07 31.66,10.9 31.67,10.91 31.67,11.24 31.78,11.35 31.78,14.15 31.88,14.25 32.55,14.25 32.7,14.1 33.51,14.1 33.87,14.45 34.58,14.45 34.65,14.38 34.65,13.56 34.42,13.34 32.98,13.34 32.7,13.06 32.7,11.79 33.59,10.9 37.83,10.9 37.98,11.05 37.98,11.38 37.73,11.63 37.73,12.52 37.9,12.7 39.58,12.7 39.71,12.57 41.16,12.57 41.44,12.29 41.44,11.05 41.26,10.87 40.19,10.87 38.92,9.6 34.42,9.6 33.82,8.99 ; 8 cut-outs
V_3P3_LAN on BOTTOM: 37.6,17.07 37.4,17.27 36.74,17.27 36.61,17.4 36.61,19.08 36.79,19.25 38.44,19.25 38.51,19.18 38.51,17.17 38.41,17.07 ; 1 cut-out
V_3P3_PCIVAUX on TOP: 117.61,203.28 117.38,203.5 117.38,205.05 117.48,205.16 119.39,205.16 119.41,205.18 119.41,205.31 119.36,205.36 117.56,205.36 117.51,205.41 117.51,205.66 122.61,205.66 122.82,205.46 122.82,203.43 122.66,203.28
V_3P3_PCIVAUX on TOP: 117.56,222.33 117.48,222.4 117.48,222.63 117.51,222.66 119.34,222.66 119.36,222.68 119.36,222.86 117.51,222.86 117.48,222.88 117.48,224.26 117.71,224.49 121.72,224.49 121.9,224.3 121.9,223.62 122.14,223.39 122.14,222.55 121.91,222.33 ; 1 cut-out
V_3P3_PCIVAUX on BOTTOM: 119.54,202.82 117.13,205.23 117.13,224.54 117.51,224.92 121.39,224.92 121.63,224.68 121.63,223.02 121.41,222.8 119.46,222.8 119.29,222.63 119.29,206.63 119.79,206.12 124.62,206.12 126.02,207.52 126.02,209.04 126.65,209.68 130.59,209.68 130.84,209.42 130.84,203.2 130.46,202.82 ; 6 cut-outs
V_5_LCD1 on BOTTOM: 34.27,105.59 33.93,105.93 33.93,106.89 33.59,107.24 32.93,107.24 32.8,107.37 32.8,108.53 32.89,108.62 35.3,108.62 35.72,108.2 35.72,106.71 35.57,106.56 35.57,106.55 34.6,105.59 ; 2 cut-outs
V_5_LCD2 on BOTTOM: 36.61,106.3 36.2,106.71 36.2,109.07 36.76,109.63 38.31,109.63 38.39,109.55 38.39,108.71 39.15,107.95 39.15,106.45 39,106.3 ; 3 cut-outs
V_5HDD on TOP: 10.8,193.37 10.02,194.16 10.02,201.14 10.45,201.57 13.09,201.57 13.83,200.84 13.83,200.25 15.4,198.68 20.94,198.68 21.04,198.58 21.04,193.62 20.78,193.37 ; 4 cut-outs
V_5P0_A on TOP: 89.82,29.92 88.43,31.32 88.43,42.88 88.81,43.26 90.23,43.26 90.56,42.93 90.56,41.88 90.3,41.63 90.3,33.71 90.99,33.02 91.96,33.02 92.11,32.87 92.11,32.13 91.98,32 91.98,30.02 91.88,29.92 ; 1 cut-out
V_5P0_A on TOP: 102.4,57.91 102.01,58.29 102.01,59.18 101.76,59.44 99.98,59.44 99.73,59.18 98.33,59.18 97.95,59.56 97.95,70.79 98.28,71.12 102.27,71.12 102.78,70.61 102.78,66.22 103.31,65.68 103.31,62.46 104.3,61.47 104.3,58.04 104.17,57.91
V_5P0_A on TOP: 157.72,91.36 157.41,91.67 157.41,97.31 158.53,98.42 158.53,103.48 155.43,106.58 155.43,110.11 154.47,111.07 154.47,121.41 156.16,123.11 156.97,123.11 157.03,123.05 157.03,122.64 157.31,122.36 158.74,122.36 159.03,122.07 159.03,121.36 158.34,120.68 157.16,120.68 156.34,119.86 156.34,112.93 157.64,111.63 157.64,107.31 160.84,104.11 160.84,103.48 162.67,101.65 162.67,99.36 161.27,97.97 161.27,96.32 160.84,95.89 160.84,92.46 160.79,92.41 159.06,92.41 158.88,92.23 158.88,91.54 158.71,91.36 ; 4 cut-outs
V_5P0_A on TOP: 88.45,222.3 87.49,223.27 87.49,224.76 87.84,225.12 90.23,225.12 90.28,225.07 90.28,222.35 90.23,222.3
V_5P0_A on BOTTOM: 88.7,47.8 88.27,48.23 88.27,51.51 92.57,55.8 92.57,63.53 93.82,64.78 101.65,64.78 101.96,64.47 101.96,59.99 101.58,59.61 99.02,59.61 98.18,58.78 98.18,55.19 90.79,47.8
V_5P0_A on L3: 159.37,93.75 156.93,91.31 156.93,89.26 156.92,89.24 156.92,87.95 155.58,86.61 154.24,86.61 153.18,87.67 153.18,88.4 153.75,88.98 153.75,93.83 157.01,97.08 158,97.08 159.37,95.71
V_5P0_A on L3: 99.6,58.67 99.6,57.28 99.98,56.9 101.58,56.9 101.96,57.28 101.96,64.31 106.59,68.94 106.59,71.07 105.72,71.93 103.03,71.93 97.8,66.7 97.8,59.79 98.64,58.95 99.32,58.95
V_5P0_A on L3: 90.76,42.72 90.76,48.44 90.03,49.17 88.55,49.17 88.55,49.15 88.04,48.64 88.04,42.93 88.81,42.16 90.2,42.16
V_5P0_HDMI_CONN on TOP: 115.5,40.55 115.38,40.67 115.38,40.98 115.38,40.99 115.38,41.33 115.53,41.48 118.37,41.48 118.4,41.44 118.4,41.19 118.36,41.15 116.38,41.15 115.78,40.55
V_5P0_HDMI_CONN on BOTTOM: 117.84,37.92 115.22,40.54 115.22,40.97 115.5,41.25 116.01,41.25 117.89,39.37 120.43,39.37 120.53,39.27 120.53,38.13 120.33,37.92 ; 2 cut-outs
V_5P0_HDMI_CONN_L on BOTTOM: 117.91,34.55 117.73,34.72 117.73,37.09 118.04,37.39 120.45,37.39 120.56,37.29 120.56,34.65 120.48,34.57 118.93,34.57 118.91,34.55
V_19_INV on TOP: 35.85,35.71 35.85,42.03 35.85,42.03 35.85,43.82 36.28,44.25 40.9,44.25 41.82,43.33 41.82,34.8 40.93,33.91 37.65,33.91
V_SM on TOP: 144.43,159.51 144.05,159.89 144.05,166.62 144.43,167 152.89,167 153.12,167.23 154.08,167.23 154.31,167 158.4,167 158.91,166.5 158.91,161.04 158.28,160.4 148.37,160.4 147.48,159.51 ; 3 cut-outs
V_SM on BOTTOM: 141.61,154.41 140.88,155.14 140.88,167.61 141.16,167.89 153.7,167.89 154.85,166.75 154.85,160.78 154.34,160.27 147.18,160.27 144.89,157.99 144.89,154.89 144.41,154.41
VGA_CORE on TOP: 108.02,87.11 106.99,88.14 106.99,105.51 107.58,106.1 110.57,106.1 111.77,104.9 115.7,104.9 116.7,103.91 116.7,88.19 115.62,87.11
VGA_CORE on TOP: 79.56,95.36 79.43,95.48 79.43,95.61 79.94,96.12 79.94,96.75 79.81,96.88 79.3,96.88 79.18,97.01 79.18,99.42 79.43,99.67 79.43,100.31 79.3,100.44 79.3,103.48 79.43,103.61 79.69,103.61 80.83,102.47 80.83,102.21 80.29,101.68 80.29,101.22 80.7,100.82 80.7,100.18 80.32,99.8 80.32,99.17 80.78,98.71 80.78,98.23 80.32,97.77 80.32,97.26 80.83,96.75 80.83,96.25 79.94,95.36
VGA_CORE on TOP: 83.24,95.48 83.24,95.61 81.46,97.39 81.46,97.9 81.97,98.4 81.97,98.79 81.46,99.29 81.46,99.8 81.97,100.31 81.97,100.56 81.46,101.07 81.46,101.71 81.97,102.21 81.97,102.47 81.84,102.6 81.84,102.85 81.97,102.98 82.35,102.98 82.86,102.47 82.86,102.21 82.23,101.58 82.23,101.07 82.86,100.44 82.86,100.31 82.23,99.67 82.23,99.42 82.35,99.29 82.35,99.17 82.86,98.66 82.86,98.53 83.11,98.28 83.5,98.28 83.62,98.4 83.75,98.4 83.75,98.91 83.24,99.42 83.24,99.67 83.75,100.18 83.75,100.69 83.24,101.2 83.24,101.45 83.75,101.96 83.75,103.23 84.26,103.74 85.4,103.74 85.65,103.48 85.65,103.23 85.02,102.6 85.02,102.34 86.16,101.2 86.16,99.42 86.67,98.91 86.67,98.28 86.16,97.77 87.31,96.63 87.31,95.99 87.05,95.74 86.67,95.74 85.94,96.47 85.94,96.6 85.48,97.05 83.12,97.05 83.01,96.95 83.01,96.52 83.68,95.86 83.68,95.56 83.6,95.48
VGA_CORE on BOTTOM: 79.94,95.61 79.81,95.74 79.81,97.52 79.43,97.9 79.43,99.29 79.3,99.29 78.8,99.8 78.8,102.34 79.69,103.23 80.07,103.23 80.45,102.85 81.59,102.85 81.65,102.79 81.72,102.85 82.35,102.85 82.48,102.72 82.48,98.91 82.35,98.79 82.1,98.79 81.59,98.28 81.59,97.77 81.46,97.64 81.08,97.64 80.7,97.26 80.7,97.03 80.96,96.78 80.96,96.37 80.83,96.25 80.55,96.25 80.45,96.14 80.45,95.74 80.32,95.61 ; 8 cut-outs
VGA_CORE on BOTTOM: 80.45,108.44 80.19,108.69 80.19,109.2 80.07,109.33 80.07,109.96 80.45,110.34 83.24,110.34 83.93,109.65 84.56,109.65 84.84,109.37 84.84,108.64 84.64,108.44 ; 4 cut-outs
VGA_CORE on BOTTOM: 82.94,94.97 82.86,95.05 82.86,96.5 83.5,97.13 83.5,100.56 83.75,100.82 83.75,103.12 84.28,103.66 84.28,103.84 84.46,104.01 84.56,104.01 84.79,104.24 84.79,104.93 84.95,105.08 85.5,105.08 85.58,105 85.58,104.29 85.17,103.89 85.17,101.86 86.26,100.77 86.26,100.56 86.19,100.49 85.6,100.49 85.47,100.62 85.47,100.9 85.18,101.2 84.64,101.2 84.51,101.07 84.51,100.56 84.69,100.39 85.07,100.39 85.15,100.31 85.15,99.55 85.27,99.42 86.16,99.42 86.8,98.79 86.8,98.4 86.42,98.02 86.42,97.39 86.67,97.13 86.67,96.68 87.2,96.14 87.2,95.91 87.1,95.81 86.72,95.81 86.42,96.12 86.42,96.24 85.55,97.1 85.55,97.61 85.4,97.76 84.72,97.76 84.56,97.61 84.56,97.03 84.31,96.77 83.75,96.77 83.52,96.55 83.52,95.13 83.37,94.98 83.11,94.98 83.11,94.97 ; 9 cut-outs
VGA_CORE on L3: 79.89,98.83 79.79,98.93 79.79,102.78 80.25,103.24 83.89,103.24 84.41,103.76 84.41,105.31 85.15,106.05 85.15,111.33 86.82,113 108.41,113 116.67,104.75 116.67,90.75 116.37,90.45 113.72,90.45 110.22,86.94 101.3,86.94 100.26,87.99 100.26,94.77 99.73,95.3 97.29,95.3 97.28,95.29 96.93,95.63 91.6,95.63 91.52,95.55 91.52,95.1 90.81,94.39 83.42,94.39 83.27,94.54 81.16,94.54 79.89,95.81
VGA_CORE on L4: 84.03,95.76 82.96,95.76 79.79,98.93 79.79,102.83 80.28,103.32 80.28,108.95 80.25,108.95 79.79,109.41 79.79,112.24 80.55,113 108.08,113 112.68,108.41 112.68,105.26 114.99,102.95 116.14,102.95 116.8,102.29 116.8,91.36 116.24,90.81 112.45,90.81 109.79,88.14 107.75,88.14 105.85,90.04 105.85,96.37 96.28,105.94 88.97,105.94 88.32,105.28 87.92,105.28 87.43,104.8 87.43,103.71 86.62,102.9 86.62,102.34 86.11,101.83 86.11,97.51 87.08,96.55 87.08,94.97 86.72,94.61 85.17,94.61
VOUT_INV on TOP: 25.55,37.6 25.36,37.8 25.36,39.67 25.56,39.88 26.96,39.88 27.34,39.5 28.99,39.5 29.12,39.37 29.12,37.97 28.99,37.85 27.19,37.85 26.94,37.6
VOUT_INV on BOTTOM: 28.89,33.99 28.48,34.39 28.48,35.18 27.85,35.81 23.27,35.81 22.89,36.2 22.89,39.62 23.4,40.13 28.23,40.13 28.61,39.75 28.61,38.4 29.01,38 31.25,38 31.34,37.91 31.34,36.31 30.82,35.79 30.82,34.37 30.44,33.99

Small or netless copper shapes (teardrops, artwork), in the pictures only: 6 on TOP, 5 on BOTTOM

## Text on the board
Ref Des/Silkscreen Bottom: F2:2A/6V | F4:1.5A/6V | F13:1.5A/6V | F3:1.5A/6V | F1:1.5A/6V | F6:1.5A/8V | LAN ID
Ref Des/Silkscreen Top: SERVICE_MODE | 1-2.CLR_CMOS | RTCRST | EMPTY(DEFAULT) | 1-2:NORMAL(DEFAULT) | 1-2:ME DISABLE | PSWD | EMPTY:CLEAR PASSWORD | EMPTY:NORMAL(DEFAULT) | SATA HDD | BATTERY | TOUCH | CONVERTER | F4:1.5A/8V | X4:25MHZ | DCIN1 | JO1110 | RJ1 | F14:2A/6V | LOUT1 | USB3 | F16:3A/32V | X8:27MHZ | NGFF_WIFI | Rev:A00 | Dell:M6RVR | WEBCAM | SSUSB2 | SSUSB1 | UHS1 | FAN_CPU | SATAP1 | SATA ODD | PWRCN1 | LVDS | X6:19.2MHZ | X7:32.768KHZ | CPU2 | USB4 | DIMM1 | For DDR3L Only | SPEAKER | OSC2:48MHZ | X3:12MHZ | PPID | Braswell AIO | 14061-1 | M6RVR | MADE IN TAIWAN | E | G | H | C | B | A | D | M2
User.26: AGND | GND
User.27: Board Accuracy Check,Jun 01 11:24:26 2015,Passed | Dummy-Static-No Shape On Layer Check,Jun 01 11:24:27 2015,Passed | Split Plane Check,Nov 10 17:03:48 2014,Passed
User.29: ByImpedance:100.0@_REF_L1=("3.5/10.0(L1)")|_REF_L6=("3.5/10.0(L6)")|Type="DP"|_REF_L4=("4.0/9.0(L4)")|_REF_L3=("4.0/9.0(L3)")|imp="100.0" | ByImpedance:110.0@_REF_L1=("nil(L1)")|_REF_L6=("nil(L6)")|Type="DP"|_REF_L4=("3.5/13.0(L4)")|_REF_L3=("3.5/13.0(L3)")|imp="110.0" | ByImpedance:27.4@_REF_L1=("12.0(L1)")|_REF_L6=("12.0(L6)")|Type="SE"|_REF_L4=("16.0(L4)")|_REF_L3=("16.0(L3)")|imp="27.4" | ByImpedance:33.0@_REF_L1=("9.0(L1)")|_REF_L6=("9.0(L6)")|Type="SE"|_REF_L4=("12.0(L4)")|_REF_L3=("12.0(L3)")|imp="33.0" | ByImpedance:34.0@_REF_L1=("8.5(L1)")|_REF_L6=("8.5(L6)")|Type="SE"|_REF_L4=("11.5(L4)")|_REF_L3=("11.5(L3)")|imp="34.0" | ByImpedance:35.0@_REF_L1=("8.0(L1)")|_REF_L6=("8.0(L6)")|Type="SE"|_REF_L4=("10.5(L4)")|_REF_L3=("10.5(L3)")|imp="35.0" | ByImpedance:37.5@_REF_L1=("7.0(L1)")|_REF_L6=("7.0(L6)")|Type="SE"|_REF_L4=("9.5(L4)")|_REF_L3=("9.5(L3)")|imp="37.5" | ByImpedance:39.0@_REF_L1=("6.5(L1)")|_REF_L6=("6.5(L6)")|Type="SE"|_REF_L4=("9.0(L4)")|_REF_L3=("9.0(L3)")|imp="39.0" | ByImpedance:40.0@_REF_L1=("6.5(L1)")|_REF_L6=("6.5(L6)")|Type="SE"|_REF_L4=("8.5(L4)")|_REF_L3=("8.5(L3)")|imp="40.0" | ByImpedance:42.0@_REF_L1=("5.5(L1)")|_REF_L6=("5.5(L6)")|Type="SE"|_REF_L4=("7.5(L4)")|_REF_L3=("7.5(L3)")|imp="42.0" | ByImpedance:45.0@_REF_L1=("5.0(L1)")|_REF_L6=("5.0(L6)")|Type="SE"|_REF_L4=("6.5(L4)")|_REF_L3=("6.5(L3)")|imp="45.0" | ByImpedance:48.0@_REF_L1=("4.5(L1)")|_REF_L6=("4.5(L6)")|Type="SE"|_REF_L4=("5.5(L4)")|_REF_L3=("5.5(L3)")|imp="48.0" | ByImpedance:50.0@_REF_L1=("4.0(L1)")|_REF_L6=("4.0(L6)")|Type="SE"|_REF_L4=("5.0(L4)")|_REF_L3=("5.0(L3)")|imp="50.0" | ByImpedance:52.0@_REF_L1=("3.5(L1)")|_REF_L6=("3.5(L6)")|Type="SE"|_REF_L4=("4.5(L4)")|_REF_L3=("4.5(L3)")|imp="52.0" | ByImpedance:55.0@_REF_L1=("nil(L1)")|_REF_L6=("nil(L6)")|Type="SE"|_REF_L4=("4.0(L4)")|_REF_L3=("4.0(L3)")|imp="55.0" | ByImpedance:65.0@_REF_L1=("8.0/6.0(L1)")|_REF_L6=("8.0/6.0(L6)")|Type="DP"|_REF_L4=("9.0/5.0(L4)")|_REF_L3=("9.0/5.0(L3)")|imp="65.0" | ByImpedance:68.0@_REF_L1=("6.5/4.0(L1)")|_REF_L6=("6.5/4.0(L6)")|Type="DP"|_REF_L4=("7.5/4.0(L4)")|_REF_L3=("7.5/4.0(L3)")|imp="68.0" | ByImpedance:70.0@_REF_L1=("7.0/6.0(L1)")|_REF_L6=("7.0/6.0(L6)")|Type="DP"|_REF_L4=("8.0/6.0(L4)")|_REF_L3=("8.0/6.0(L3)")|imp="70.0" | ByImpedance:72.0@_REF_L1=("7.0/8.0(L1)")|_REF_L6=("7.0/8.0(L6)")|Type="DP"|_REF_L4=("7.0/5.0(L4)")|_REF_L3=("7.0/5.0(L3)")|imp="72.0" | ByImpedance:75.0@_REF_L1=("6.0/6.0(L1)")|_REF_L6=("6.0/6.0(L6)")|Type="DP"|_REF_L4=("7.0/6.0(L4)")|_REF_L3=("7.0/6.0(L3)")|imp="75.0" | ByImpedance:80.0@_REF_L1=("5.0/5.0(L1)")|_REF_L6=("5.0/5.0(L6)")|Type="DP"|_REF_L4=("6.0/6.0(L4)")|_REF_L3=("6.0/6.0(L3)")|imp="80.0" | ByImpedance:85.0@_REF_L1=("5.0/8.0(L1)" "4.0/4.5(L1)")|_REF_L6=("5.0/8.0(L6)" "4.0/4.5(L6)")|Type="DP"|_REF_L4=("5.0/5.5(L4)")|_REF_L3=("5.0/5.5(L3)")|imp="85.0" | ByImpedance:90.0@_REF_L1=("4.0/6.0(L1)")|_REF_L6=("4.0/6.0(L6)")|Type="DP"|_REF_L4=("5.0/8.0(L4)" "4.0/5.0(L4)")|_REF_L3=("5.0/8.0(L3)" "4.0/5.0(L3)")|imp="90.0" | ByImpedance:93.0@_REF_L1=("4.0/8.0(L1)" "3.5/5.5(L1)")|_REF_L6=("4.0/8.0(L6)" "3.5/5.5(L6)")|Type="DP"|_REF_L4=("5.0/9.0(L4)" "4.0/5.5(L4)")|_REF_L3=("5.0/9.0(L3)" "4.0/5.5(L3)")|imp="93.0" | ByImpedance:95.0@_REF_L1=("4.0/10.0(L1)" "3.5/6.0(L1)")|_REF_L6=("4.0/10.0(L6)" "3.5/6.0(L6)")|Type="DP"|_REF_L4=("4.0/6.5(L4)")|_REF_L3=("4.0/6.5(L3)")|imp="95.0" | LayerIndex:nil | Source:6-1.2-7c.xls | artWorks:("_REF_L3" "_REF_L4" "_REF_L6" "_REF_L1") | gtImpOutlineUsed:BOARD GEOMETRY/PANEL_OUTLINE
User.30: GND | AGND
User.32: This gerber is just for your reference to find the DP impedance traces in layer L1. | DP IMPEDANCE TABLE: L1 | * - Denotes that WIDTH | is NOT used in this layer | inside board outline. | IMP(Ohm) | 65.0 | 68.0 | 70.0 | 72.0 | 75.0 | 80.0 | 85.0 | 90.0 | 93.0 | 95.0 | 100.0 | 110.0 | WIDTH(mils) | *8.0/6.0 | *6.5/4.0 | *7.0/6.0 | *7.0/8.0 | *6.0/6.0 | 5.0/5.0 | *5.0/8.0 | 4.0/4.5 | 4.0/6.0 | 4.0/8.0 | *3.5/5.5 | *4.0/10.0 | *3.5/6.0 | 3.5/10.0 | *nil | TYPE | DP
User.34: This gerber is just for your reference to find the SE impedance traces in layer L1. | SE IMPEDANCE TABLE: L1 | * - Denotes that WIDTH | is NOT used in this layer | inside board outline. | IMP(Ohm) | 27.4 | 33.0 | 34.0 | 35.0 | 37.5 | 39.0 | 40.0 | 42.0 | 45.0 | 48.0 | 50.0 | 52.0 | 55.0 | WIDTH(mils) | 12.0 | 9.0 | *8.5 | 8.0 | 7.0 | 6.5 | *5.5 | 5.0 | *4.5 | 4.0 | 3.5 | *nil | TYPE | SE
User.36: This gerber is just for your reference to find the DP impedance traces in layer L3. | DP IMPEDANCE TABLE: L3 | * - Denotes that WIDTH | is NOT used in this layer | inside board outline. | IMP(Ohm) | 65.0 | 68.0 | 70.0 | 72.0 | 75.0 | 80.0 | 85.0 | 90.0 | 93.0 | 95.0 | 100.0 | 110.0 | WIDTH(mils) | *9.0/5.0 | *7.5/4.0 | *8.0/6.0 | *7.0/5.0 | *7.0/6.0 | 6.0/6.0 | 5.0/5.5 | *5.0/8.0 | *4.0/5.0 | *5.0/9.0 | *4.0/5.5 | *4.0/6.5 | 4.0/9.0 | *3.5/13.0 | TYPE | DP
User.38: This gerber is just for your reference to find the SE impedance traces in layer L3. | SE IMPEDANCE TABLE: L3 | * - Denotes that WIDTH | is NOT used in this layer | inside board outline. | IMP(Ohm) | 27.4 | 33.0 | 34.0 | 35.0 | 37.5 | 39.0 | 40.0 | 42.0 | 45.0 | 48.0 | 50.0 | 52.0 | 55.0 | WIDTH(mils) | *16.0 | 12.0 | *11.5 | *10.5 | *9.5 | *9.0 | 8.5 | *7.5 | 6.5 | *5.5 | 5.0 | *4.5 | 4.0 | TYPE | SE
User.40: This gerber is just for your reference to find the DP impedance traces in layer L4. | DP IMPEDANCE TABLE: L4 | * - Denotes that WIDTH | is NOT used in this layer | inside board outline. | IMP(Ohm) | 65.0 | 68.0 | 70.0 | 72.0 | 75.0 | 80.0 | 85.0 | 90.0 | 93.0 | 95.0 | 100.0 | 110.0 | WIDTH(mils) | *9.0/5.0 | *7.5/4.0 | *8.0/6.0 | *7.0/5.0 | *7.0/6.0 | 6.0/6.0 | 5.0/5.5 | *5.0/8.0 | 4.0/5.0 | *5.0/9.0 | *4.0/5.5 | *4.0/6.5 | 4.0/9.0 | *3.5/13.0 | TYPE | DP
User.42: This gerber is just for your reference to find the SE impedance traces in layer L4. | SE IMPEDANCE TABLE: L4 | * - Denotes that WIDTH | is NOT used in this layer | inside board outline. | IMP(Ohm) | 27.4 | 33.0 | 34.0 | 35.0 | 37.5 | 39.0 | 40.0 | 42.0 | 45.0 | 48.0 | 50.0 | 52.0 | 55.0 | WIDTH(mils) | *16.0 | 12.0 | *11.5 | *10.5 | *9.5 | *9.0 | 8.5 | *7.5 | 6.5 | *5.5 | 5.0 | *4.5 | 4.0 | TYPE | SE
User.44: This gerber is just for your reference to find the DP impedance traces in layer L6. | DP IMPEDANCE TABLE: L6 | * - Denotes that WIDTH | is NOT used in this layer | inside board outline. | IMP(Ohm) | 65.0 | 68.0 | 70.0 | 72.0 | 75.0 | 80.0 | 85.0 | 90.0 | 93.0 | 95.0 | 100.0 | 110.0 | WIDTH(mils) | *8.0/6.0 | *6.5/4.0 | *7.0/6.0 | *7.0/8.0 | *6.0/6.0 | 5.0/5.0 | *5.0/8.0 | 4.0/4.5 | 4.0/6.0 | *4.0/8.0 | *3.5/5.5 | 4.0/10.0 | *3.5/6.0 | 3.5/10.0 | *nil | TYPE | DP
User.45: This gerber is just for you reference to find the differential traces in layer BOTTOM | This gerber is just for you reference to find the differential traces in layer L3 | This gerber is just for you reference to find the differential traces in layer L4 | This gerber is just for you reference to find the differential traces in layer TOP | Note:Refer to DRILL layer for ELLIPSE drill direction | FIGURE | SIZE | 10.0 | 12.0 | 16.0 | 20.0 | 28.0 | 30.0 | 36.0 | 37.0 | 39.0 | 40.0 | 60.0 | 91.0 | 109.0 | 158.0 | 42.0 | 44.0 | 50.0 | 54.0 | 63.0 | 67.0 | 86.0 | 138.0 | 178.0 | 48.0x16.0 | 56.0x24.0 | 60.0x24.0 | 60.0x28.0 | 67.0x28.0 | 67.0x30.0 | 67.0x32.0 | 91.0x28.0 | 156.0x32.0 | 166.0x32.0 | 197.0x178.0 | DRILL CHART: TOP to BOTTOM | ALL UNITS ARE IN MILS | PLATED | NON-PLATED | QTY | 2049 | 1416 | 837 | 40 | 18 | 14 | 8 | 12 | 4 | 1 | 5 | 3 | 2 | 7 | This gerber is just for your reference to find the SE impedance traces in layer L6. | SE IMPEDANCE TABLE: L6 | * - Denotes that WIDTH | is NOT used in this layer | inside board outline. | Model | Braswell AIO | PCB_NO | 14061 | VER. | Layer | DRILL | L1 | L2VCC | L3 | TMASK | TPLACE | TSILK | TSMD | Designer | MOSSE | Date | 06/03/2015 | IMP(Ohm) | 27.4 | 33.0 | 34.0 | 35.0 | 37.5 | 45.0 | 48.0 | 52.0 | 55.0 | WIDTH(mils) | 9.0 | *8.5 | 8.0 | 7.0 | 6.5 | *5.5 | 5.0 | *4.5 | 4.0 | 3.5 | *nil | TYPE | SE | BMASK | BPLACE | BSILK | BSMD | L4 | L5GND | L6
